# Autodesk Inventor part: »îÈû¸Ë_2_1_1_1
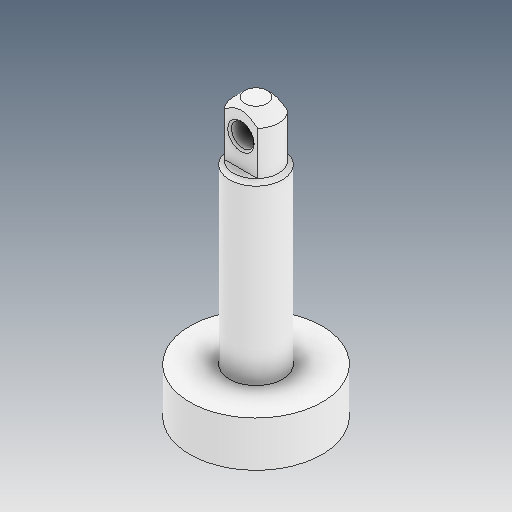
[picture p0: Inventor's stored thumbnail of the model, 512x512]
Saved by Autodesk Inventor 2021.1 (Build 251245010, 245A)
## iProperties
Created: 2021-05
Part Number: »îÈû¸Ë_2_1_1_1
Material: Ogólny
Document SubType Name: Modeling
Designer: user
Density: 1 g/cm^3
Appearance: Domyślna
Author: user
Revision Number: ÈÎºÎ
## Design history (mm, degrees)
feature "ÊäÈë1"
node "Bryła1"
